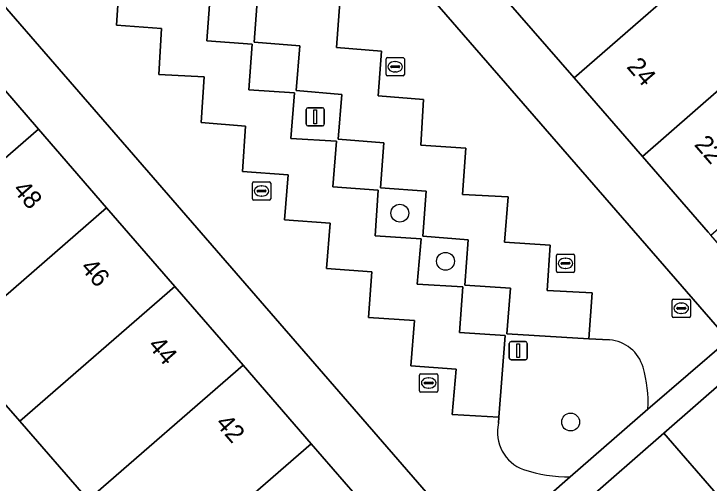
# Model space of a CAD drawing. Extents: x 155887 to 156869, y 383880 to 384678.
# Drawn here: x 156334.36 to 156372.39, y 384097.03 to 384122.68 of the extents above; entities that cross this region are included whole.
import ezdxf

# ---------------------------------------------------------------- set-up
doc = ezdxf.new("R2010")
doc.units = 0
for name, color, linetype in [('IMGEO_Berm_groen', 7, 'Continuous'), ('IMGEO_Boom', 7, 'Continuous'), ('IMGEO_Brandkraan', 7, 'Continuous'), ('IMGEO_Erf', 7, 'Continuous'), ('IMGEO_Kolk', 7, 'Continuous'), ('IMGEO_Lichtmast', 7, 'Continuous'), ('IMGEO_Pand', 7, 'Continuous'), ('IMGEO_Pand_nummerreeks', 7, 'Continuous'), ('IMGEO_Parkeervlak_open', 7, 'Continuous'), ('IMGEO_Rijbaan_lokaal_open', 7, 'Continuous'), ('IMGEO_Verkeerseiland_groen', 7, 'Continuous'), ('IMGEO_Voetpad_open', 7, 'Continuous')]:
    doc.layers.add(name, color=color, linetype=linetype)

msp = doc.modelspace()

# ---------------------------------------------------------------- linework, layer by layer
at = {"layer": 'IMGEO_Berm_groen'}
for points in [[(156345.089, 384123.687), (156344.909, 384121.211), (156347.391, 384121.03), (156347.213, 384118.534), (156349.704, 384118.366), (156349.505, 384115.866), (156351.999, 384115.72), (156351.812, 384113.225), (156354.291, 384113.051), (156354.125, 384110.551), (156356.631, 384110.385), (156356.428, 384107.91), (156358.925, 384107.753), (156358.744, 384105.253), (156361.227, 384105.088), (156360.883, 384100.625), (156360.866, 384100.295)], [(156366.943, 384104.851), (156365.822, 384104.918), (156361.324, 384105.188), (156361.521, 384107.677), (156359.026, 384107.845), (156359.215, 384110.326), (156356.726, 384110.521), (156356.916, 384112.984), (156354.408, 384113.168), (156354.592, 384115.641), (156352.1, 384115.84), (156352.291, 384118.271), (156349.791, 384118.488), (156349.992, 384120.94), (156347.496, 384121.14), (156347.688, 384123.622)], [(156364.8, 384097.36), (156369.05, 384101.069)]]:
    msp.add_lwpolyline(points, dxfattribs=at)
for centre, radius, start, end in [((156366.792, 384102.79), 2.066, 15.9236, 85.8042), ((156362.323, 384101.432), 6.737, 356.9088, 16.601), ((156362.982, 384099.808), 2.171, 167.0414, 250.0779), ((156364.808, 384105.652), 8.292, 251.9736, 269.9455)]:
    msp.add_arc(centre, radius, start, end, dxfattribs=at)
at = {"layer": 'IMGEO_Boom'}
for centre in [(156355.471, 384111.785), (156357.971, 384109.154), (156364.816, 384100.364)]:
    msp.add_circle(centre, 0.489, dxfattribs=at)
at = {"layer": 'IMGEO_Brandkraan'}
for p, q in [((156370.37, 384106.16), (156370.37, 384107.012)), ((156370.445, 384107.086), (156371.297, 384107.086)), ((156370.858, 384106.866), (156370.883, 384106.866)), ((156371.371, 384107.012), (156371.371, 384106.16)), ((156370.629, 384106.58), (156370.629, 384106.592)), ((156371.067, 384106.543), (156370.669, 384106.543)), ((156370.672, 384106.629), (156371.07, 384106.629)), ((156371.113, 384106.592), (156371.113, 384106.58)), ((156371.297, 384106.086), (156370.445, 384106.086)), ((156370.881, 384106.306), (156370.856, 384106.306))]:
    msp.add_line(p, q, dxfattribs=at)
for points in [[(156370.37, 384106.16), (156370.37, 384107.012)], [(156370.445, 384107.086), (156371.297, 384107.086)], [(156371.371, 384107.012), (156371.371, 384106.16)], [(156371.297, 384106.086), (156370.445, 384106.086)]]:
    msp.add_lwpolyline(points, dxfattribs=at)
for centre, radius, start, end in [((156370.447, 384107.01), 0.0765, 91.552, 178.448), ((156370.447, 384107.01), 0.0765, 91.552, 178.448), ((156371.295, 384107.01), 0.0765, 1.552, 88.448), ((156371.295, 384107.01), 0.0765, 1.552, 88.448), ((156370.669, 384106.589), 0.0403, 85.8775, 175.7526), ((156370.666, 384106.579), 0.0366, 178.938, 274.7102), ((156371.07, 384106.586), 0.043, 264.8664, 352.4533), ((156371.074, 384106.591), 0.0386, 1.7309, 96.639), ((156370.447, 384106.162), 0.0765, 181.552, 268.448), ((156370.447, 384106.162), 0.0765, 181.552, 268.448), ((156371.295, 384106.162), 0.0765, 271.552, 358.448), ((156371.295, 384106.162), 0.0765, 271.552, 358.448)]:
    msp.add_arc(centre, radius, start, end, dxfattribs=at)
for centre, major_axis, ratio, start_param, end_param in [((156370.857, 384106.586), (-0.387, 0.002), 0.722429, 4.712389, 7.853982), ((156370.882, 384106.586), (-0.39, 0.002), 0.717154, 1.570796, 4.712389)]:
    msp.add_ellipse(centre, major_axis=major_axis, ratio=ratio, start_param=start_param, end_param=end_param, dxfattribs=at)
at = {"layer": 'IMGEO_Erf'}
for points in [[(156375.732, 384106.848), (156372.481, 384110.588), (156372.345, 384110.746), (156368.744, 384114.889), (156365.007, 384119.189), (156361.269, 384123.49), (156357.533, 384127.79), (156353.795, 384132.09), (156350.058, 384136.391), (156346.321, 384140.691), (156342.43, 384145.168), (156340.156, 384143.199), (156340.225, 384143.101), (156373.448, 384104.867), (156375.066, 384106.258)], [(156359.895, 384093.079), (156326.654, 384131.386), (156324.334, 384129.488), (156328.231, 384124.995), (156331.964, 384120.692), (156335.697, 384116.388), (156339.43, 384112.085), (156343.163, 384107.781), (156346.896, 384103.477), (156350.629, 384099.174), (156354.231, 384095.022), (156354.362, 384094.871), (156357.607, 384091.13), (156358.294, 384091.715)]]:
    msp.add_lwpolyline(points, close=True, dxfattribs=at)
msp.add_lwpolyline([(156338.413, 384096.115), (156334.671, 384100.407), (156330.929, 384104.7), (156327.186, 384108.993), (156328.695, 384110.304), (156328.537, 384110.485), (156325.862, 384113.553), (156325.025, 384114.514), (156324.953, 384114.597), (156323.445, 384113.286), (156319.701, 384117.58), (156319.076, 384118.297), (156315.791, 384122.065), (156306.714, 384114.217)], dxfattribs=at)
at = {"layer": 'IMGEO_Kolk'}
for p, q in [((156354.718, 384119.367), (156354.718, 384120.219)), ((156354.793, 384120.293), (156355.645, 384120.293)), ((156355.206, 384120.073), (156355.231, 384120.073)), ((156355.719, 384120.219), (156355.719, 384119.367)), ((156354.977, 384119.787), (156354.977, 384119.799)), ((156355.415, 384119.75), (156355.017, 384119.75)), ((156355.02, 384119.836), (156355.418, 384119.836)), ((156355.461, 384119.799), (156355.461, 384119.787)), ((156355.645, 384119.293), (156354.793, 384119.293)), ((156355.229, 384119.513), (156355.204, 384119.513)), ((156347.405, 384112.571), (156347.405, 384113.423)), ((156347.48, 384113.497), (156348.332, 384113.497)), ((156347.893, 384113.277), (156347.918, 384113.277)), ((156348.406, 384113.423), (156348.406, 384112.571)), ((156347.664, 384112.991), (156347.664, 384113.003)), ((156348.102, 384112.954), (156347.704, 384112.954)), ((156347.707, 384113.04), (156348.105, 384113.04)), ((156348.148, 384113.003), (156348.148, 384112.991)), ((156348.332, 384112.497), (156347.48, 384112.497)), ((156347.916, 384112.717), (156347.891, 384112.717)), ((156364.036, 384108.614), (156364.036, 384109.466)), ((156364.111, 384109.54), (156364.963, 384109.54)), ((156365.037, 384109.466), (156365.037, 384108.614)), ((156364.295, 384109.034), (156364.295, 384109.046)), ((156364.338, 384109.083), (156364.736, 384109.083)), ((156364.524, 384109.32), (156364.549, 384109.32)), ((156364.779, 384109.046), (156364.779, 384109.034)), ((156364.733, 384108.997), (156364.335, 384108.997)), ((156364.547, 384108.76), (156364.522, 384108.76)), ((156364.963, 384108.54), (156364.111, 384108.54)), ((156356.627, 384103.001), (156357.479, 384103.001)), ((156356.552, 384102.075), (156356.552, 384102.927)), ((156357.04, 384102.781), (156357.065, 384102.781)), ((156357.553, 384102.927), (156357.553, 384102.075)), ((156356.811, 384102.495), (156356.811, 384102.507)), ((156357.249, 384102.458), (156356.851, 384102.458)), ((156356.854, 384102.544), (156357.252, 384102.544)), ((156357.063, 384102.221), (156357.038, 384102.221)), ((156357.295, 384102.507), (156357.295, 384102.495)), ((156357.479, 384102.001), (156356.627, 384102.001))]:
    msp.add_line(p, q, dxfattribs=at)
for points in [[(156354.718, 384119.367), (156354.718, 384120.219)], [(156354.793, 384120.293), (156355.645, 384120.293)], [(156355.719, 384120.219), (156355.719, 384119.367)], [(156355.645, 384119.293), (156354.793, 384119.293)], [(156347.405, 384112.571), (156347.405, 384113.423)], [(156347.48, 384113.497), (156348.332, 384113.497)], [(156348.406, 384113.423), (156348.406, 384112.571)], [(156348.332, 384112.497), (156347.48, 384112.497)], [(156364.036, 384108.614), (156364.036, 384109.466)], [(156364.111, 384109.54), (156364.963, 384109.54)], [(156365.037, 384109.466), (156365.037, 384108.614)], [(156364.963, 384108.54), (156364.111, 384108.54)], [(156356.627, 384103.001), (156357.479, 384103.001)], [(156356.552, 384102.075), (156356.552, 384102.927)], [(156357.553, 384102.927), (156357.553, 384102.075)], [(156357.479, 384102.001), (156356.627, 384102.001)]]:
    msp.add_lwpolyline(points, dxfattribs=at)
for centre, radius, start, end in [((156354.795, 384120.217), 0.0765, 91.552, 178.448), ((156354.795, 384120.217), 0.0765, 91.552, 178.448), ((156355.643, 384120.217), 0.0765, 1.552, 88.448), ((156355.643, 384120.217), 0.0765, 1.552, 88.448), ((156355.017, 384119.796), 0.0403, 85.8775, 175.7526), ((156355.014, 384119.786), 0.0366, 178.938, 274.7102), ((156355.418, 384119.793), 0.043, 264.8664, 352.4533), ((156355.422, 384119.798), 0.0386, 1.7309, 96.639), ((156354.795, 384119.369), 0.0765, 181.552, 268.448), ((156354.795, 384119.369), 0.0765, 181.552, 268.448), ((156355.643, 384119.369), 0.0765, 271.552, 358.448), ((156355.643, 384119.369), 0.0765, 271.552, 358.448), ((156347.482, 384113.421), 0.0765, 91.552, 178.448), ((156347.482, 384113.421), 0.0765, 91.552, 178.448), ((156348.33, 384113.421), 0.0765, 1.552, 88.448), ((156348.33, 384113.421), 0.0765, 1.552, 88.448), ((156347.704, 384113), 0.0403, 85.8775, 175.7526), ((156347.701, 384112.99), 0.0366, 178.938, 274.7102), ((156348.105, 384112.997), 0.043, 264.8664, 352.4533), ((156348.109, 384113.002), 0.0386, 1.7309, 96.639), ((156347.482, 384112.573), 0.0765, 181.552, 268.448), ((156347.482, 384112.573), 0.0765, 181.552, 268.448), ((156348.33, 384112.573), 0.0765, 271.552, 358.448), ((156348.33, 384112.573), 0.0765, 271.552, 358.448), ((156364.113, 384109.464), 0.0765, 91.552, 178.448), ((156364.113, 384109.464), 0.0765, 91.552, 178.448), ((156364.961, 384109.464), 0.0765, 1.552, 88.448), ((156364.961, 384109.464), 0.0765, 1.552, 88.448), ((156364.335, 384109.043), 0.0403, 85.8775, 175.7526), ((156364.332, 384109.033), 0.0366, 178.938, 274.7102), ((156364.736, 384109.04), 0.043, 264.8664, 352.4533), ((156364.74, 384109.045), 0.0386, 1.7309, 96.639), ((156364.113, 384108.616), 0.0765, 181.552, 268.448), ((156364.113, 384108.616), 0.0765, 181.552, 268.448), ((156364.961, 384108.616), 0.0765, 271.552, 358.448), ((156364.961, 384108.616), 0.0765, 271.552, 358.448), ((156356.629, 384102.925), 0.0765, 91.552, 178.448), ((156356.629, 384102.925), 0.0765, 91.552, 178.448), ((156357.477, 384102.925), 0.0765, 1.552, 88.448), ((156357.477, 384102.925), 0.0765, 1.552, 88.448), ((156356.851, 384102.504), 0.0403, 85.8775, 175.7526), ((156356.848, 384102.494), 0.0366, 178.938, 274.7102), ((156357.252, 384102.501), 0.043, 264.8664, 352.4533), ((156357.256, 384102.506), 0.0386, 1.7309, 96.639), ((156356.629, 384102.077), 0.0765, 181.552, 268.448), ((156356.629, 384102.077), 0.0765, 181.552, 268.448), ((156357.477, 384102.077), 0.0765, 271.552, 358.448), ((156357.477, 384102.077), 0.0765, 271.552, 358.448)]:
    msp.add_arc(centre, radius, start, end, dxfattribs=at)
for centre, major_axis, ratio, start_param, end_param in [((156355.205, 384119.793), (-0.387, 0.002), 0.722429, 4.712389, 7.853982), ((156355.23, 384119.793), (-0.39, 0.002), 0.717154, 1.570796, 4.712389), ((156347.892, 384112.997), (-0.387, 0.002), 0.722429, 4.712389, 7.853982), ((156347.917, 384112.997), (-0.39, 0.002), 0.717154, 1.570796, 4.712389), ((156364.523, 384109.04), (-0.387, 0.002), 0.722429, 4.712389, 7.853982), ((156364.548, 384109.04), (-0.39, 0.002), 0.717154, 1.570796, 4.712389), ((156357.039, 384102.501), (-0.387, 0.002), 0.722429, 4.712389, 7.853982), ((156357.064, 384102.501), (-0.39, 0.002), 0.717154, 1.570796, 4.712389)]:
    msp.add_ellipse(centre, major_axis=major_axis, ratio=ratio, start_param=start_param, end_param=end_param, dxfattribs=at)
at = {"layer": 'IMGEO_Lichtmast'}
for p, q in [((156350.346, 384116.654), (156350.346, 384117.454)), ((156350.346, 384117.454), (156350.346, 384116.654)), ((156350.446, 384117.554), (156351.236, 384117.554)), ((156351.236, 384117.554), (156350.446, 384117.554)), ((156351.336, 384117.454), (156351.336, 384116.654)), ((156351.336, 384116.654), (156351.336, 384117.454)), ((156351.236, 384116.554), (156350.446, 384116.554)), ((156350.446, 384116.554), (156351.236, 384116.554)), ((156361.455, 384103.865), (156361.455, 384104.665)), ((156361.455, 384104.665), (156361.455, 384103.865)), ((156361.555, 384104.765), (156362.345, 384104.765)), ((156362.345, 384104.765), (156361.555, 384104.765)), ((156362.445, 384104.665), (156362.445, 384103.865)), ((156362.445, 384103.865), (156362.445, 384104.665)), ((156362.345, 384103.765), (156361.555, 384103.765)), ((156361.555, 384103.765), (156362.345, 384103.765))]:
    msp.add_line(p, q, dxfattribs=at)
for points in [[(156350.766, 384117.429), (156350.916, 384117.429), (156350.916, 384116.679), (156350.766, 384116.679), (156350.766, 384117.429)], [(156361.875, 384104.64), (156362.025, 384104.64), (156362.025, 384103.89), (156361.875, 384103.89), (156361.875, 384104.64)]]:
    msp.add_lwpolyline(points, dxfattribs=at)
for centre, start, end in [((156350.446, 384117.454), 90, 180), ((156350.446, 384117.454), 90, 180), ((156351.236, 384117.454), 0, 90), ((156351.236, 384117.454), 360, 90), ((156350.446, 384116.654), 180, 270), ((156350.446, 384116.654), 180, 270), ((156351.236, 384116.654), 270, 0), ((156351.236, 384116.654), 270, 0), ((156361.555, 384104.665), 90, 180), ((156361.555, 384104.665), 90, 180), ((156362.345, 384104.665), 0, 90), ((156362.345, 384104.665), 360, 90), ((156361.555, 384103.865), 180, 270), ((156361.555, 384103.865), 180, 270), ((156362.345, 384103.865), 270, 0), ((156362.345, 384103.865), 270, 0)]:
    msp.add_arc(centre, 0.1, start, end, dxfattribs=at)
at = {"layer": 'IMGEO_Pand'}
for points in [[(156365.007, 384119.189), (156373.522, 384126.611), (156369.789, 384130.915), (156361.269, 384123.49)], [(156377.256, 384122.306), (156379.058, 384123.876), (156375.313, 384128.172), (156373.522, 384126.611), (156365.007, 384119.189), (156368.744, 384114.889)], [(156382.27, 384119.115), (156382.155, 384119.248), (156380.873, 384118.136), (156377.256, 384122.306), (156368.744, 384114.889), (156372.345, 384110.746), (156372.481, 384110.588)], [(156335.697, 384116.388), (156331.964, 384120.692), (156324.953, 384114.597), (156325.025, 384114.514), (156325.862, 384113.553), (156328.537, 384110.485), (156328.695, 384110.304)], [(156339.43, 384112.085), (156335.697, 384116.388), (156328.695, 384110.304), (156327.186, 384108.993), (156330.929, 384104.7)], [(156330.929, 384104.7), (156334.671, 384100.407), (156343.163, 384107.781), (156339.43, 384112.085)], [(156338.413, 384096.115), (156346.896, 384103.477), (156343.163, 384107.781), (156334.671, 384100.407)], [(156350.629, 384099.174), (156346.896, 384103.477), (156338.413, 384096.115), (156342.157, 384091.821)], [(156350.629, 384099.174), (156342.157, 384091.821), (156345.757, 384087.691), (156344.387, 384086.497), (156344.503, 384086.363), (156354.362, 384094.871), (156354.231, 384095.022)]]:
    msp.add_lwpolyline(points, close=True, dxfattribs=at)
at = {"layer": 'IMGEO_Parkeervlak_open'}
for points in [[(156340.128, 384124.539), (156339.969, 384122.064), (156342.439, 384121.883), (156342.281, 384119.373), (156344.761, 384119.246), (156344.594, 384116.735), (156347.035, 384116.548), (156346.864, 384114.068), (156349.353, 384113.885), (156349.168, 384111.423), (156351.657, 384111.239), (156351.453, 384108.752), (156353.942, 384108.574), (156353.761, 384106.087), (156356.27, 384105.911), (156356.069, 384103.439), (156358.548, 384103.254), (156358.341, 384100.78), (156360.883, 384100.625), (156361.227, 384105.088), (156358.744, 384105.253), (156358.925, 384107.753), (156356.428, 384107.91), (156356.631, 384110.385), (156354.125, 384110.551), (156354.291, 384113.051), (156351.812, 384113.225), (156351.999, 384115.72), (156349.505, 384115.866), (156349.704, 384118.366), (156347.213, 384118.534), (156347.391, 384121.03), (156344.909, 384121.211), (156345.089, 384123.687)], [(156347.688, 384123.622), (156347.496, 384121.14), (156349.992, 384120.94), (156349.791, 384118.488), (156352.291, 384118.271), (156352.1, 384115.84), (156354.592, 384115.641), (156354.408, 384113.168), (156356.916, 384112.984), (156356.726, 384110.521), (156359.215, 384110.326), (156359.026, 384107.845), (156361.521, 384107.677), (156361.324, 384105.188), (156365.822, 384104.918), (156366, 384107.436), (156363.527, 384107.557), (156363.698, 384110.045), (156361.202, 384110.195), (156361.394, 384112.686), (156358.906, 384112.815), (156359.083, 384115.333), (156356.616, 384115.508), (156356.762, 384117.993), (156354.294, 384118.2), (156354.471, 384120.649), (156352.008, 384120.848), (156352.192, 384123.315)]]:
    msp.add_lwpolyline(points, dxfattribs=at)
at = {"layer": 'IMGEO_Rijbaan_lokaal_open'}
for points in [[(156369.05, 384101.069), (156373.448, 384104.867), (156340.225, 384143.101), (156334.608, 384138.293), (156333.088, 384136.971), (156326.654, 384131.386), (156359.895, 384093.079), (156364.8, 384097.36)], [(156360.866, 384100.295), (156360.883, 384100.625), (156358.341, 384100.78), (156358.548, 384103.254), (156356.069, 384103.439), (156356.27, 384105.911), (156353.761, 384106.087), (156353.942, 384108.574), (156351.453, 384108.752), (156351.657, 384111.239), (156349.168, 384111.423), (156349.353, 384113.885), (156346.864, 384114.068), (156347.035, 384116.548), (156344.594, 384116.735), (156344.761, 384119.246), (156342.281, 384119.373), (156342.439, 384121.883), (156339.969, 384122.064), (156340.128, 384124.539)], [(156352.192, 384123.315), (156352.008, 384120.848), (156354.471, 384120.649), (156354.294, 384118.2), (156356.762, 384117.993), (156356.616, 384115.508), (156359.083, 384115.333), (156358.906, 384112.815), (156361.394, 384112.686), (156361.202, 384110.195), (156363.698, 384110.045), (156363.527, 384107.557), (156366, 384107.436), (156365.822, 384104.918), (156366.943, 384104.851)]]:
    msp.add_lwpolyline(points, dxfattribs=at)
msp.add_lwpolyline([(156376.376, 384099.303), (156373.38, 384102.774), (156369.92, 384099.753), (156372.888, 384096.324)], close=True, dxfattribs=at)
for centre, radius, start, end in [((156366.792, 384102.79), 2.066, 15.9236, 85.8042), ((156362.323, 384101.432), 6.737, 356.9088, 16.601), ((156362.982, 384099.808), 2.171, 167.0414, 250.0779), ((156364.808, 384105.652), 8.292, 251.9736, 269.9455)]:
    msp.add_arc(centre, radius, start, end, dxfattribs=at)
at = {"layer": 'IMGEO_Verkeerseiland_groen'}
msp.add_lwpolyline([(156372.888, 384096.324), (156369.92, 384099.753), (156365.454, 384095.854), (156368.427, 384092.437), (156370.508, 384094.247)], close=True, dxfattribs=at)
at = {"layer": 'IMGEO_Voetpad_open'}
msp.add_lwpolyline([(156373.448, 384104.867), (156369.05, 384101.069), (156364.8, 384097.36), (156359.895, 384093.079), (156358.294, 384091.715), (156357.607, 384091.13), (156347.788, 384082.594), (156339.965, 384075.806), (156338.946, 384074.921), (156332.882, 384069.66), (156324.054, 384062.007), (156319.938, 384058.416), (156320.966, 384057.246), (156358.182, 384089.505), (156361.976, 384092.817), (156365.454, 384095.854), (156369.92, 384099.753), (156373.38, 384102.774)], dxfattribs=at)

# ---------------------------------------------------------------- texts
at = {"layer": 'IMGEO_Pand_nummerreeks'}
for s, rotation, p in [('24', 310.9949, (156367.842, 384119.77)), ('22', 310.9923, (156371.541, 384115.514)), ('48', 310.9376, (156334.257, 384113.044)), ('46', 310.9395, (156337.952, 384108.784)), ('44', 310.9395, (156341.649, 384104.522)), ('42', 310.9395, (156345.344, 384100.263))]:
    msp.add_text(s, height=1, rotation=rotation, dxfattribs=at).set_placement(p)

doc.saveas('drawing.dxf')
